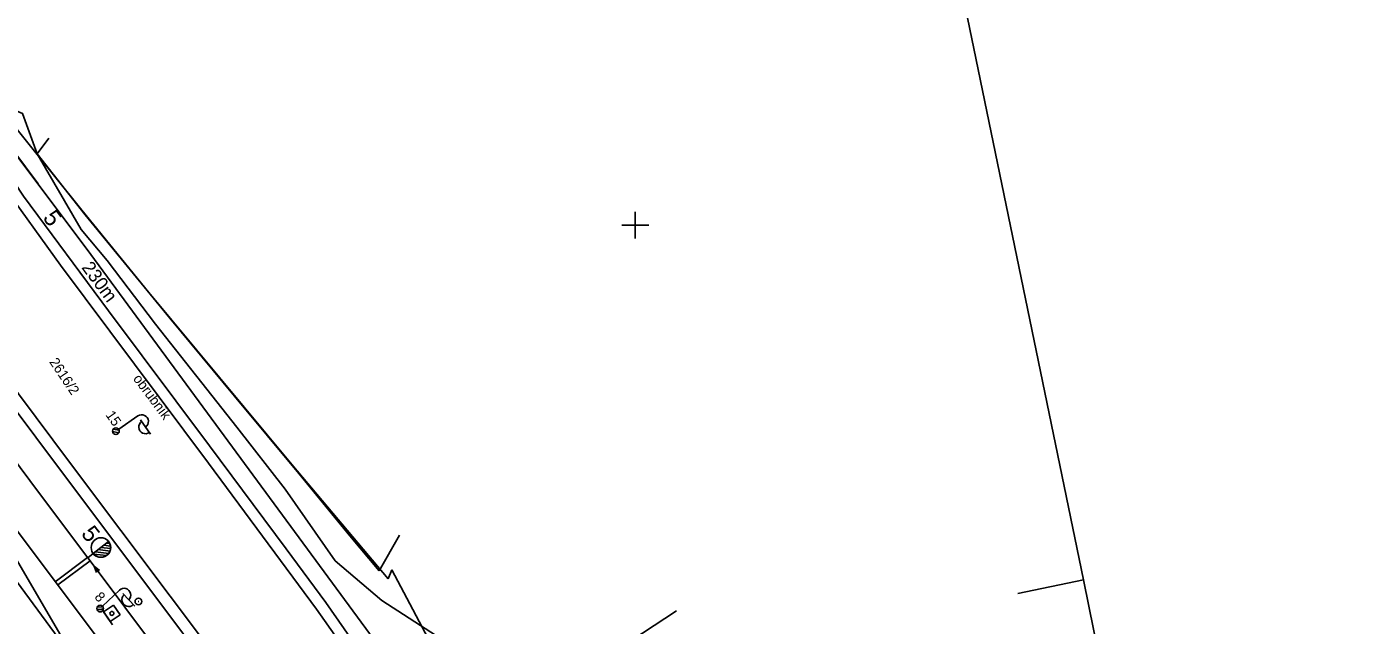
# Model space of a CAD drawing. Extents: x -804166 to -803706, y -1151030 to -1150147.
# Drawn here: x -803991 to -803790.5, y -1150359.8 to -1150270.3 of the extents above; entities that cross this region are included whole.
import ezdxf

# ---------------------------------------------------------------- set-up
doc = ezdxf.new("R2010")
doc.units = 0
for name, color, linetype in [('0381KM032-037P - Vrstva 1', 7, 'Continuous'), ('0381KM032-037P - Vrstva 17', 7, 'Continuous'), ('0381KM032-037P - Vrstva 2', 7, 'Continuous'), ('0381KM032-037P - Vrstva 25', 7, 'Continuous'), ('0381KM032-037P - Vrstva 27', 7, 'Continuous'), ('0381KM032-037P - Vrstva 3', 7, 'Continuous'), ('0381KM032-037P - Vrstva 4', 7, 'Continuous'), ('0381KM032-037P - Vrstva 49', 7, 'Continuous'), ('0381KM032-037P - Vrstva 51', 7, 'Continuous'), ('0381KM032-037P - Vrstva 57', 7, 'Continuous'), ('0381KM032-037P - Vrstva 7', 7, 'Continuous'), ('formát', 7, 'Continuous'), ('hran DP - hran DP', 7, 'Continuous'), ('krizky_1000 - Vrstva 1', 7, 'Continuous'), ('vyt_sit - polygon', 7, 'Continuous')]:
    doc.layers.add(name, color=color, linetype=linetype)

msp = doc.modelspace()

# ---------------------------------------------------------------- linework, layer by layer
at = {"layer": '0381KM032-037P - Vrstva 1'}
for points in [[(-804087.93, -1150205.28), (-804078.71, -1150215.28), (-804072.37, -1150222.52), (-804072.08, -1150222.85), (-804071.47, -1150223.58), (-804065.48, -1150230.82), (-804059.47, -1150238.51), (-804055.55, -1150243.68), (-804054.36, -1150245.27), (-804043.89, -1150259.22), (-804035.37, -1150270.61), (-804034.4, -1150271.93), (-804017.97, -1150293.92), (-804002.6, -1150314.46), (-803985.38, -1150337.43), (-803955.87, -1150376.72)], [(-804089.35, -1150206.44), (-804078.67, -1150220.7), (-804069.15, -1150233.38), (-804067.86, -1150235.11), (-804059.28, -1150246.53), (-804058.07, -1150248.16), (-804048.7, -1150260.65), (-804037.85, -1150275.13), (-804021.63, -1150296.76), (-804006.14, -1150317.34), (-803988.98, -1150340.29), (-803981.9, -1150349.73)], [(-804090.39, -1150214.38), (-804086.65, -1150219.55), (-804073.82, -1150237.11), (-804072.56, -1150238.83), (-804064.05, -1150250.31), (-804062.81, -1150251.97), (-804052.29, -1150266.05), (-804042.5, -1150279.11), (-804026.55, -1150300.33), (-804011.27, -1150320.63), (-803993.37, -1150344.49), (-803965.17, -1150382.07), (-803953.84, -1150397.19)], [(-804093.97, -1150217.42), (-804088.17, -1150225.67), (-804077.51, -1150240.28), (-804068.52, -1150252.21), (-804067.31, -1150253.81), (-804055.01, -1150270.12), (-804046.09, -1150281.93), (-804030.05, -1150303.21), (-804014.76, -1150323.52), (-803996.92, -1150347.35), (-803968.88, -1150385.42), (-803942.6, -1150419.03)], [(-804011.14, -1150262.39), (-804005.45, -1150273.41), (-803998.73, -1150284.85), (-803991.51, -1150295.63), (-803978.8, -1150312.77), (-803963.69, -1150332.99), (-803952.21, -1150348.36), (-803946.3, -1150356.39), (-803941.6, -1150363.14), (-803936.71, -1150370.83), (-803932.05, -1150378.84), (-803927.78, -1150386.91), (-803924.06, -1150395.18), (-803920.62, -1150403.65), (-803918.06, -1150410.86), (-803915.07, -1150420.32), (-803912.96, -1150427.25), (-803910.49, -1150435.34), (-803907.33, -1150445.05), (-803903.67, -1150454.38), (-803897.94, -1150464.6), (-803891.97, -1150476.6)], [(-803981.9, -1150349.73), (-803980.96, -1150350.97), (-803971.94, -1150363.03), (-803962.12, -1150376.15)], [(-803981.9, -1150349.73), (-803980.96, -1150350.97), (-803971.94, -1150363.03), (-803963.66, -1150377.12)]]:
    msp.add_lwpolyline(points, dxfattribs=at)
at = {"layer": '0381KM032-037P - Vrstva 17'}
for p, q in [((-803987.75, -1150286.99), (-803989.47, -1150289.34)), ((-803935.29, -1150346.34), (-803938.3, -1150351.66))]:
    msp.add_line(p, q, dxfattribs=at)
msp.add_lwpolyline([(-803938.3, -1150351.66), (-803942.72, -1150346.43), (-803950.36, -1150337.11), (-803959.95, -1150325.57), (-803969.63, -1150313.89), (-803978.45, -1150303.11), (-803982.31, -1150298.44), (-803989.47, -1150289.34)], dxfattribs=at)
at = {"layer": '0381KM032-037P - Vrstva 2'}
for p, q in [((-803981.09, -1150349.09), (-803978.8, -1150347.27)), ((-803978.8, -1150347.27), (-803981.09, -1150349.09)), ((-803980.35, -1150348.49), (-803978.58, -1150348.7)), ((-803979.93, -1150348.17), (-803978.49, -1150348.33)), ((-803979.51, -1150347.84), (-803978.5, -1150347.96)), ((-803979.09, -1150347.51), (-803978.62, -1150347.56)), ((-803981.1, -1150349.09), (-803981.9, -1150349.73)), ((-803981.09, -1150349.09), (-803981.09, -1150349.09)), ((-803981.02, -1150349.17), (-803979.13, -1150349.39)), ((-803980.76, -1150348.82), (-803978.78, -1150349.06))]:
    msp.add_line(p, q, dxfattribs=at)
for points in [[(-803981.9, -1150349.73), (-803980.96, -1150350.97), (-803971.94, -1150363.03), (-803962.12, -1150376.15)], [(-803980.18, -1150351.59), (-803980.96, -1150350.97), (-803980.59, -1150351.9)]]:
    msp.add_lwpolyline(points, dxfattribs=at)
msp.add_circle((-803979.94, -1150348.18), 1.46, dxfattribs=at)
msp.add_arc((-803979.95, -1150348.18), 1.46, 218.2901, 38.251, dxfattribs=at)
at = {"layer": '0381KM032-037P - Vrstva 25'}
for p, q in [((-803977.29, -1150330.5), (-803974.41, -1150328.51)), ((-803978.09, -1150330.47), (-803977.23, -1150330.63)), ((-803974.01, -1150329.08), (-803972.53, -1150331.22)), ((-803978.2, -1150330.83), (-803977.25, -1150331.01)), ((-803979.7, -1150356.96), (-803977.17, -1150354.55)), ((-803976.69, -1150355.05), (-803974.89, -1150356.93)), ((-803980.55, -1150357.43), (-803979.59, -1150357.46)), ((-803980.5, -1150357.06), (-803979.62, -1150357.08))]:
    msp.add_line(p, q, dxfattribs=at)
for centre in [(-803977.7, -1150330.78), (-803977.7, -1150330.78), (-803980.07, -1150357.31), (-803980.07, -1150357.31)]:
    msp.add_circle(centre, 0.5, dxfattribs=at)
for centre, start, end in [((-803973.84, -1150329.33), 304.6353, 124.6353), ((-803973.28, -1150330.16), 123.9327, 305.3379), ((-803976.48, -1150355.27), 313.6296, 133.6296), ((-803975.8, -1150356), 132.927, 314.3322)]:
    msp.add_arc(centre, 1, start, end, dxfattribs=at)
at = {"layer": '0381KM032-037P - Vrstva 27'}
msp.add_line((-803974.39, -1150356.24), (-803974.29, -1150356.24), dxfattribs=at)
msp.add_circle((-803974.34, -1150356.24), 0.5, dxfattribs=at)
at = {"layer": '0381KM032-037P - Vrstva 3'}
for p, q in [((-803979.88, -1150357.31), (-803978.21, -1150359.75)), ((-803978.08, -1150356.8), (-803979.54, -1150357.8)), ((-803979.54, -1150357.8), (-803978.54, -1150359.26)), ((-803978.54, -1150359.26), (-803977.08, -1150358.26)), ((-803977.08, -1150358.26), (-803978.08, -1150356.8)), ((-803948.98, -1150393.6), (-803893.86, -1150357.66))]:
    msp.add_line(p, q, dxfattribs=at)
msp.add_circle((-803978.31, -1150358.03), 0.296, dxfattribs=at)
at = {"layer": '0381KM032-037P - Vrstva 4'}
for points in [[(-804015.09, -1150257.7), (-804005.61, -1150276.65), (-803997.81, -1150289.61), (-803985.99, -1150305.97), (-803963.83, -1150335.54), (-803947.69, -1150357.39), (-803941.6, -1150366.02), (-803933.49, -1150379.54), (-803925.57, -1150395.83), (-803919.57, -1150411.36), (-803915.11, -1150425.7)], [(-804033.34, -1150270.47), (-804023.51, -1150283.74), (-804006.75, -1150306.05), (-804002.75, -1150311.23), (-803984.52, -1150335.59), (-803962.04, -1150365.45)]]:
    msp.add_lwpolyline(points, dxfattribs=at)
at = {"layer": '0381KM032-037P - Vrstva 49'}
for points in [[(-804010.87, -1150255.86), (-804001.61, -1150274.67), (-803994.7, -1150286.68), (-803981.46, -1150304.36), (-803936.05, -1150366.09), (-803921.77, -1150392.54), (-803912.22, -1150419.28), (-803908.81, -1150430.91)], [(-804010.87, -1150255.86), (-804010.87, -1150255.86), (-804001.65, -1150274.6), (-803994.86, -1150286.39), (-803989.31, -1150293.81), (-803989.41, -1150293.74)], [(-803998.25, -1150280.5), (-803991.69, -1150283.27), (-803989.47, -1150289.34)], [(-803989.47, -1150289.34), (-803982.88, -1150300.61), (-803979.03, -1150305.25), (-803971.78, -1150314.79), (-803959.62, -1150330.2), (-803952.37, -1150339.47), (-803944.88, -1150350.15), (-803937.92, -1150356.12), (-803929.73, -1150361.39)]]:
    msp.add_lwpolyline(points, dxfattribs=at)
at = {"layer": '0381KM032-037P - Vrstva 51'}
msp.add_lwpolyline([(-804015.09, -1150257.7), (-804005.61, -1150276.65), (-803997.81, -1150289.61), (-803985.99, -1150305.97), (-803963.83, -1150335.54), (-803947.69, -1150357.39), (-803941.6, -1150366.02), (-803933.49, -1150379.54), (-803925.57, -1150395.83), (-803919.57, -1150411.36), (-803915.11, -1150425.7)], dxfattribs=at)
at = {"layer": '0381KM032-037P - Vrstva 7'}
for p, q in [((-803981.94, -1150349.67), (-803986.77, -1150353.29)), ((-803981.58, -1150350.15), (-803986.41, -1150353.77))]:
    msp.add_line(p, q, dxfattribs=at)
at = {"layer": 'formát'}
for p, q in [((-803875.43, -1150147.35), (-803832.97, -1150353.01)), ((-803842.77, -1150355.03), (-803832.97, -1150353.01)), ((-803842.77, -1150355.03), (-803832.97, -1150353.01)), ((-803832.97, -1150353.01), (-803790.51, -1150558.67))]:
    msp.add_line(p, q, dxfattribs=at)
at = {"layer": 'hran DP - hran DP'}
for p, q in [((-803997.02, -1150280.06), (-803982.8, -1150297.76)), ((-803982.8, -1150297.76), (-803972.77, -1150310.06)), ((-803972.77, -1150310.06), (-803951.37, -1150335.75)), ((-803951.37, -1150335.75), (-803936.98, -1150352.88)), ((-803936.98, -1150352.88), (-803936.41, -1150351.52)), ((-803936.41, -1150351.52), (-803914.94, -1150392.05))]:
    msp.add_line(p, q, dxfattribs=at)
at = {"layer": 'krizky_1000 - Vrstva 1'}
for points in [[(-803900, -1150298), (-803900, -1150302)], [(-803902, -1150300), (-803898, -1150300)]]:
    msp.add_lwpolyline(points, dxfattribs=at)
at = {"layer": 'vyt_sit - polygon'}
msp.add_line((-803955.93, -1150412.63), (-804016.51, -1150309.12), dxfattribs=at)

# ---------------------------------------------------------------- texts
at = {"layer": '0381KM032-037P - Vrstva 1'}
for s, height, rotation, p in [('5', 2.5, 307.3088, (-803988.73, -1150298.92)), ('230m', 2, 306.5584, (-803982.92, -1150306.33))]:
    msp.add_text(s, height=height, rotation=rotation, dxfattribs=at).set_placement(p)
at = {"layer": '0381KM032-037P - Vrstva 2'}
msp.add_text('5', height=2.5, rotation=308.2705, dxfattribs=at).set_placement((-803983.01, -1150346.15))
at = {"layer": '0381KM032-037P - Vrstva 25'}
for s, rotation, p in [('15', 304.6353, (-803979.31, -1150328.36)), ('8', 313.6296, (-803981, -1150355.67))]:
    msp.add_text(s, height=1.5, rotation=rotation, dxfattribs=at).set_placement(p)
at = {"layer": '0381KM032-037P - Vrstva 51'}
msp.add_text('obrubník', height=1.5, rotation=306.842, dxfattribs=at).set_placement((-803975.21, -1150322.95))
at = {"layer": '0381KM032-037P - Vrstva 57'}
msp.add_text('2616/2', height=1.5, rotation=303.9651, dxfattribs=at).set_placement((-803987.73, -1150320.43))

doc.saveas('drawing.dxf')
